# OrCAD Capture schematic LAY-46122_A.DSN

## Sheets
1 PAGE1: size A3; rev: 1; note: HIGH POWER MODULE
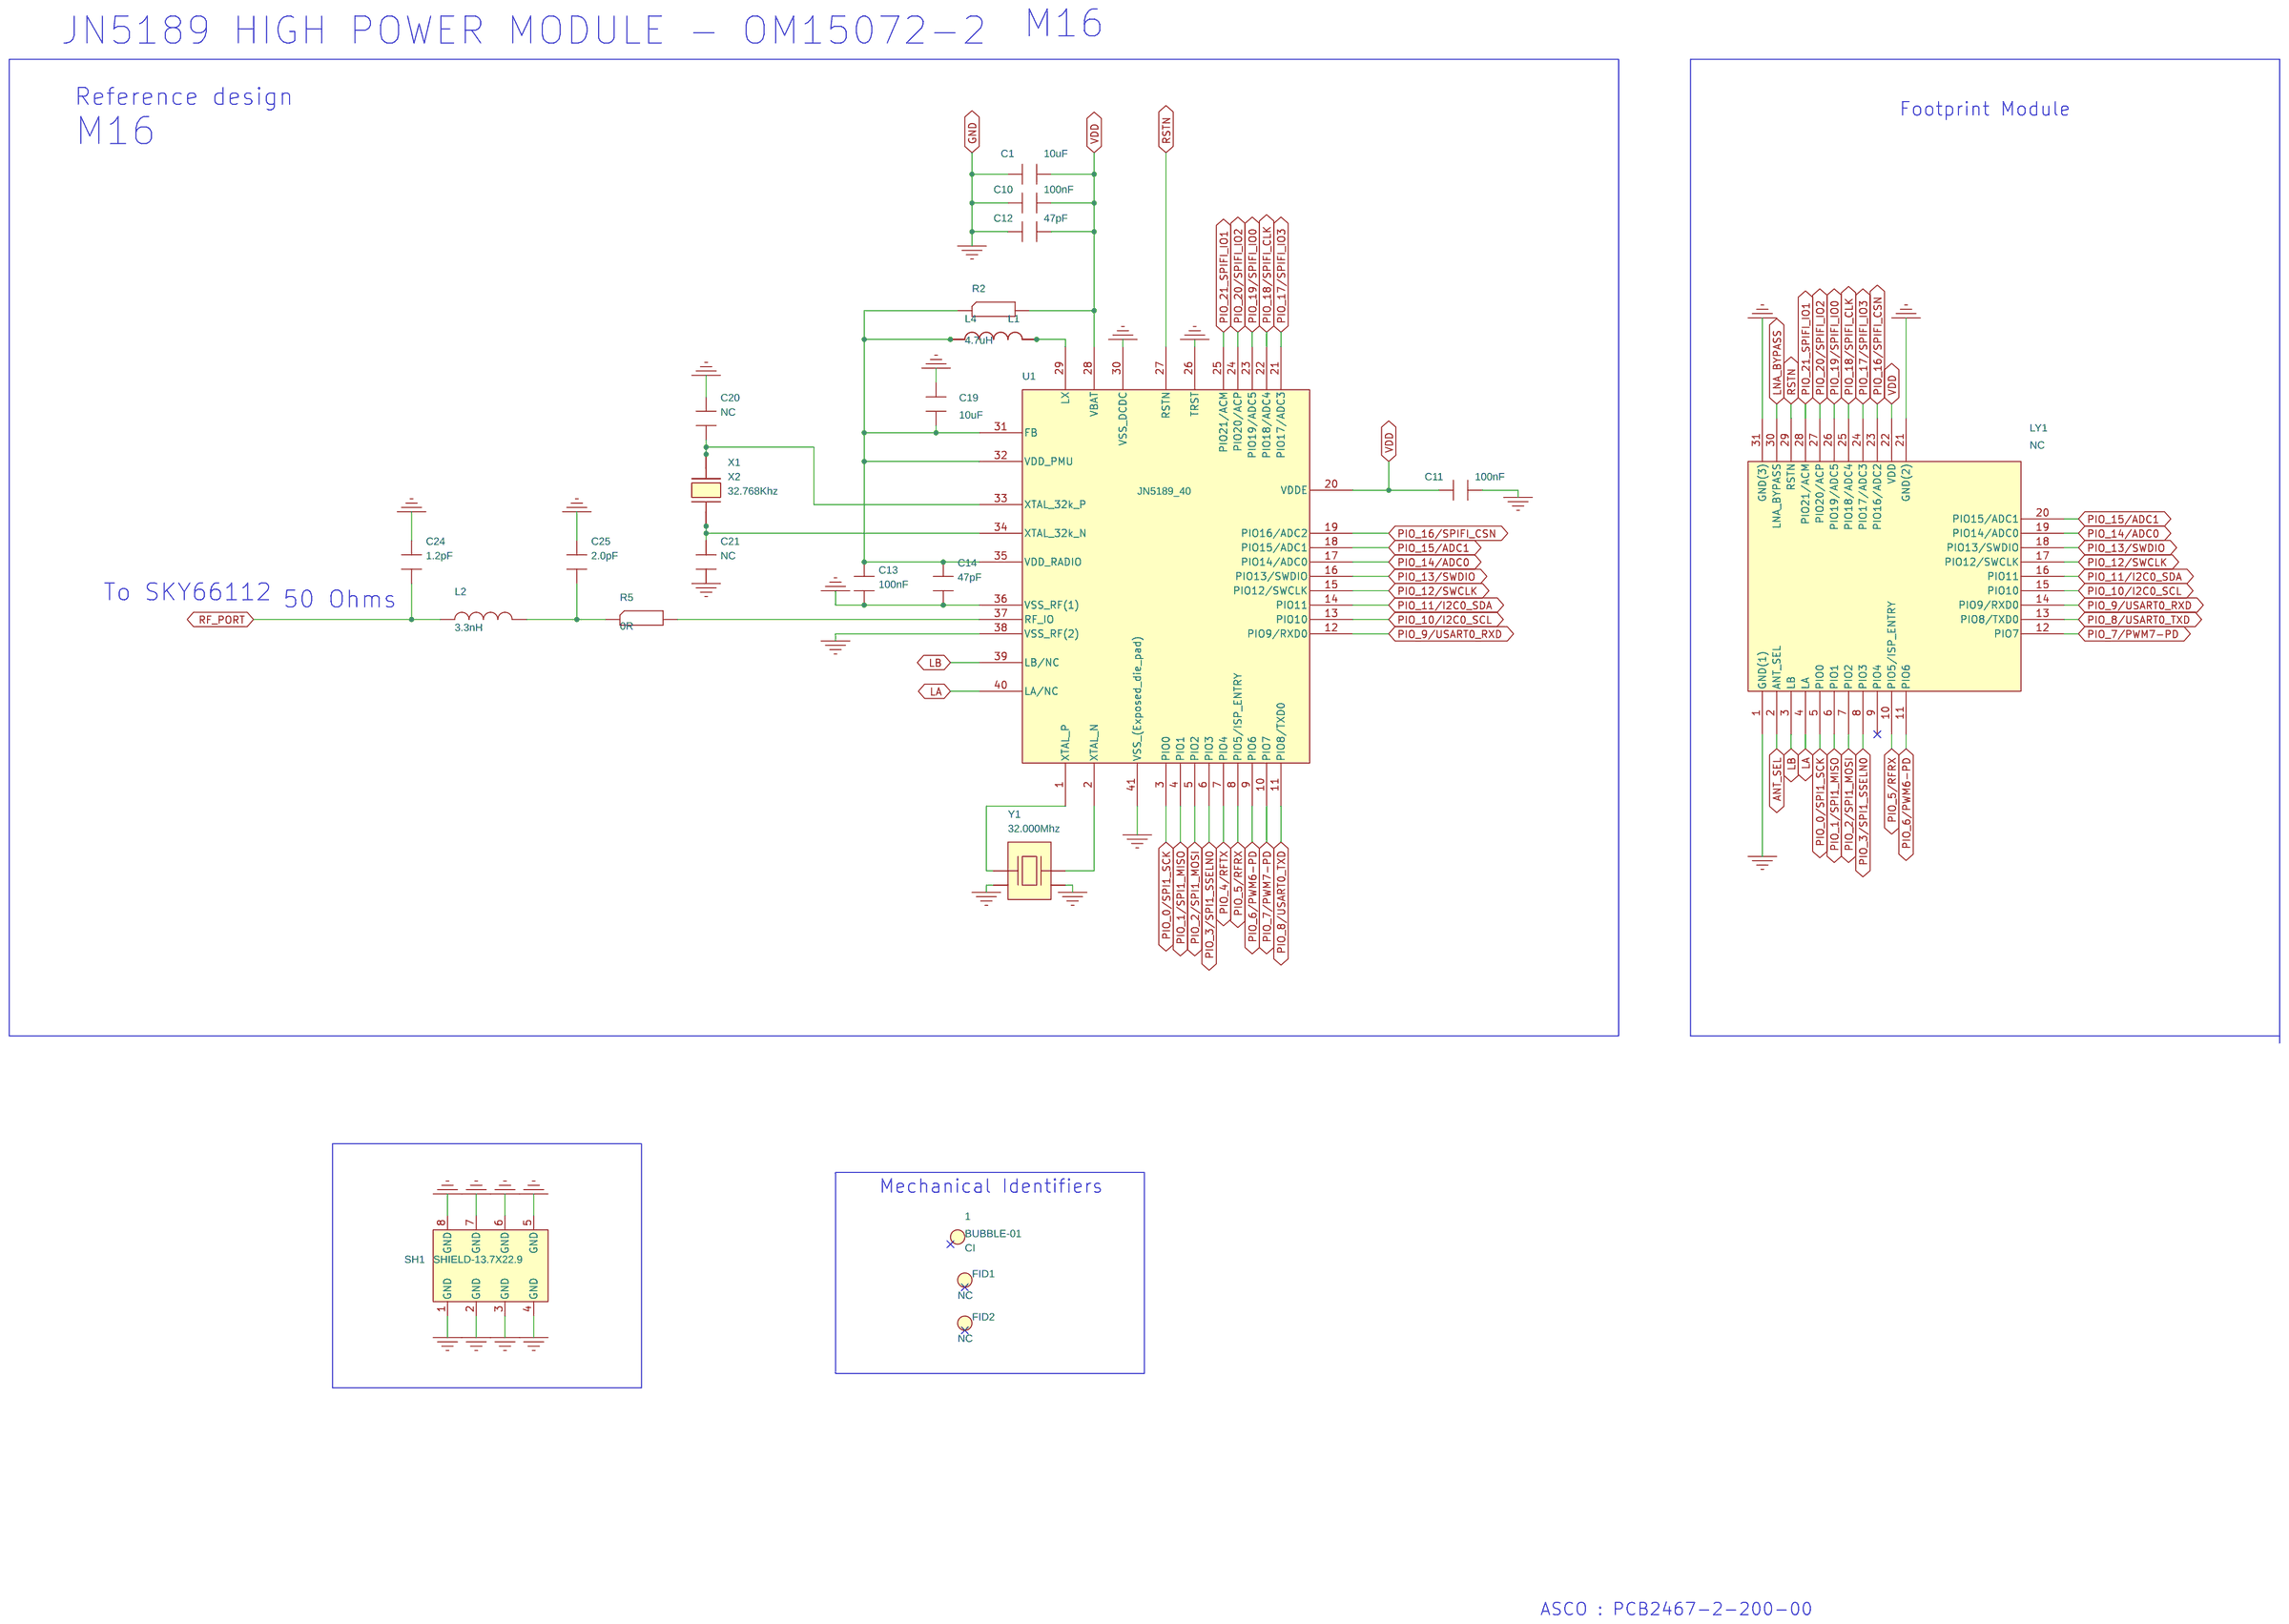
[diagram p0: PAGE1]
2 PAGE2: size A3; note: EXTERNAL_AMPLIFICATOR_MODULE
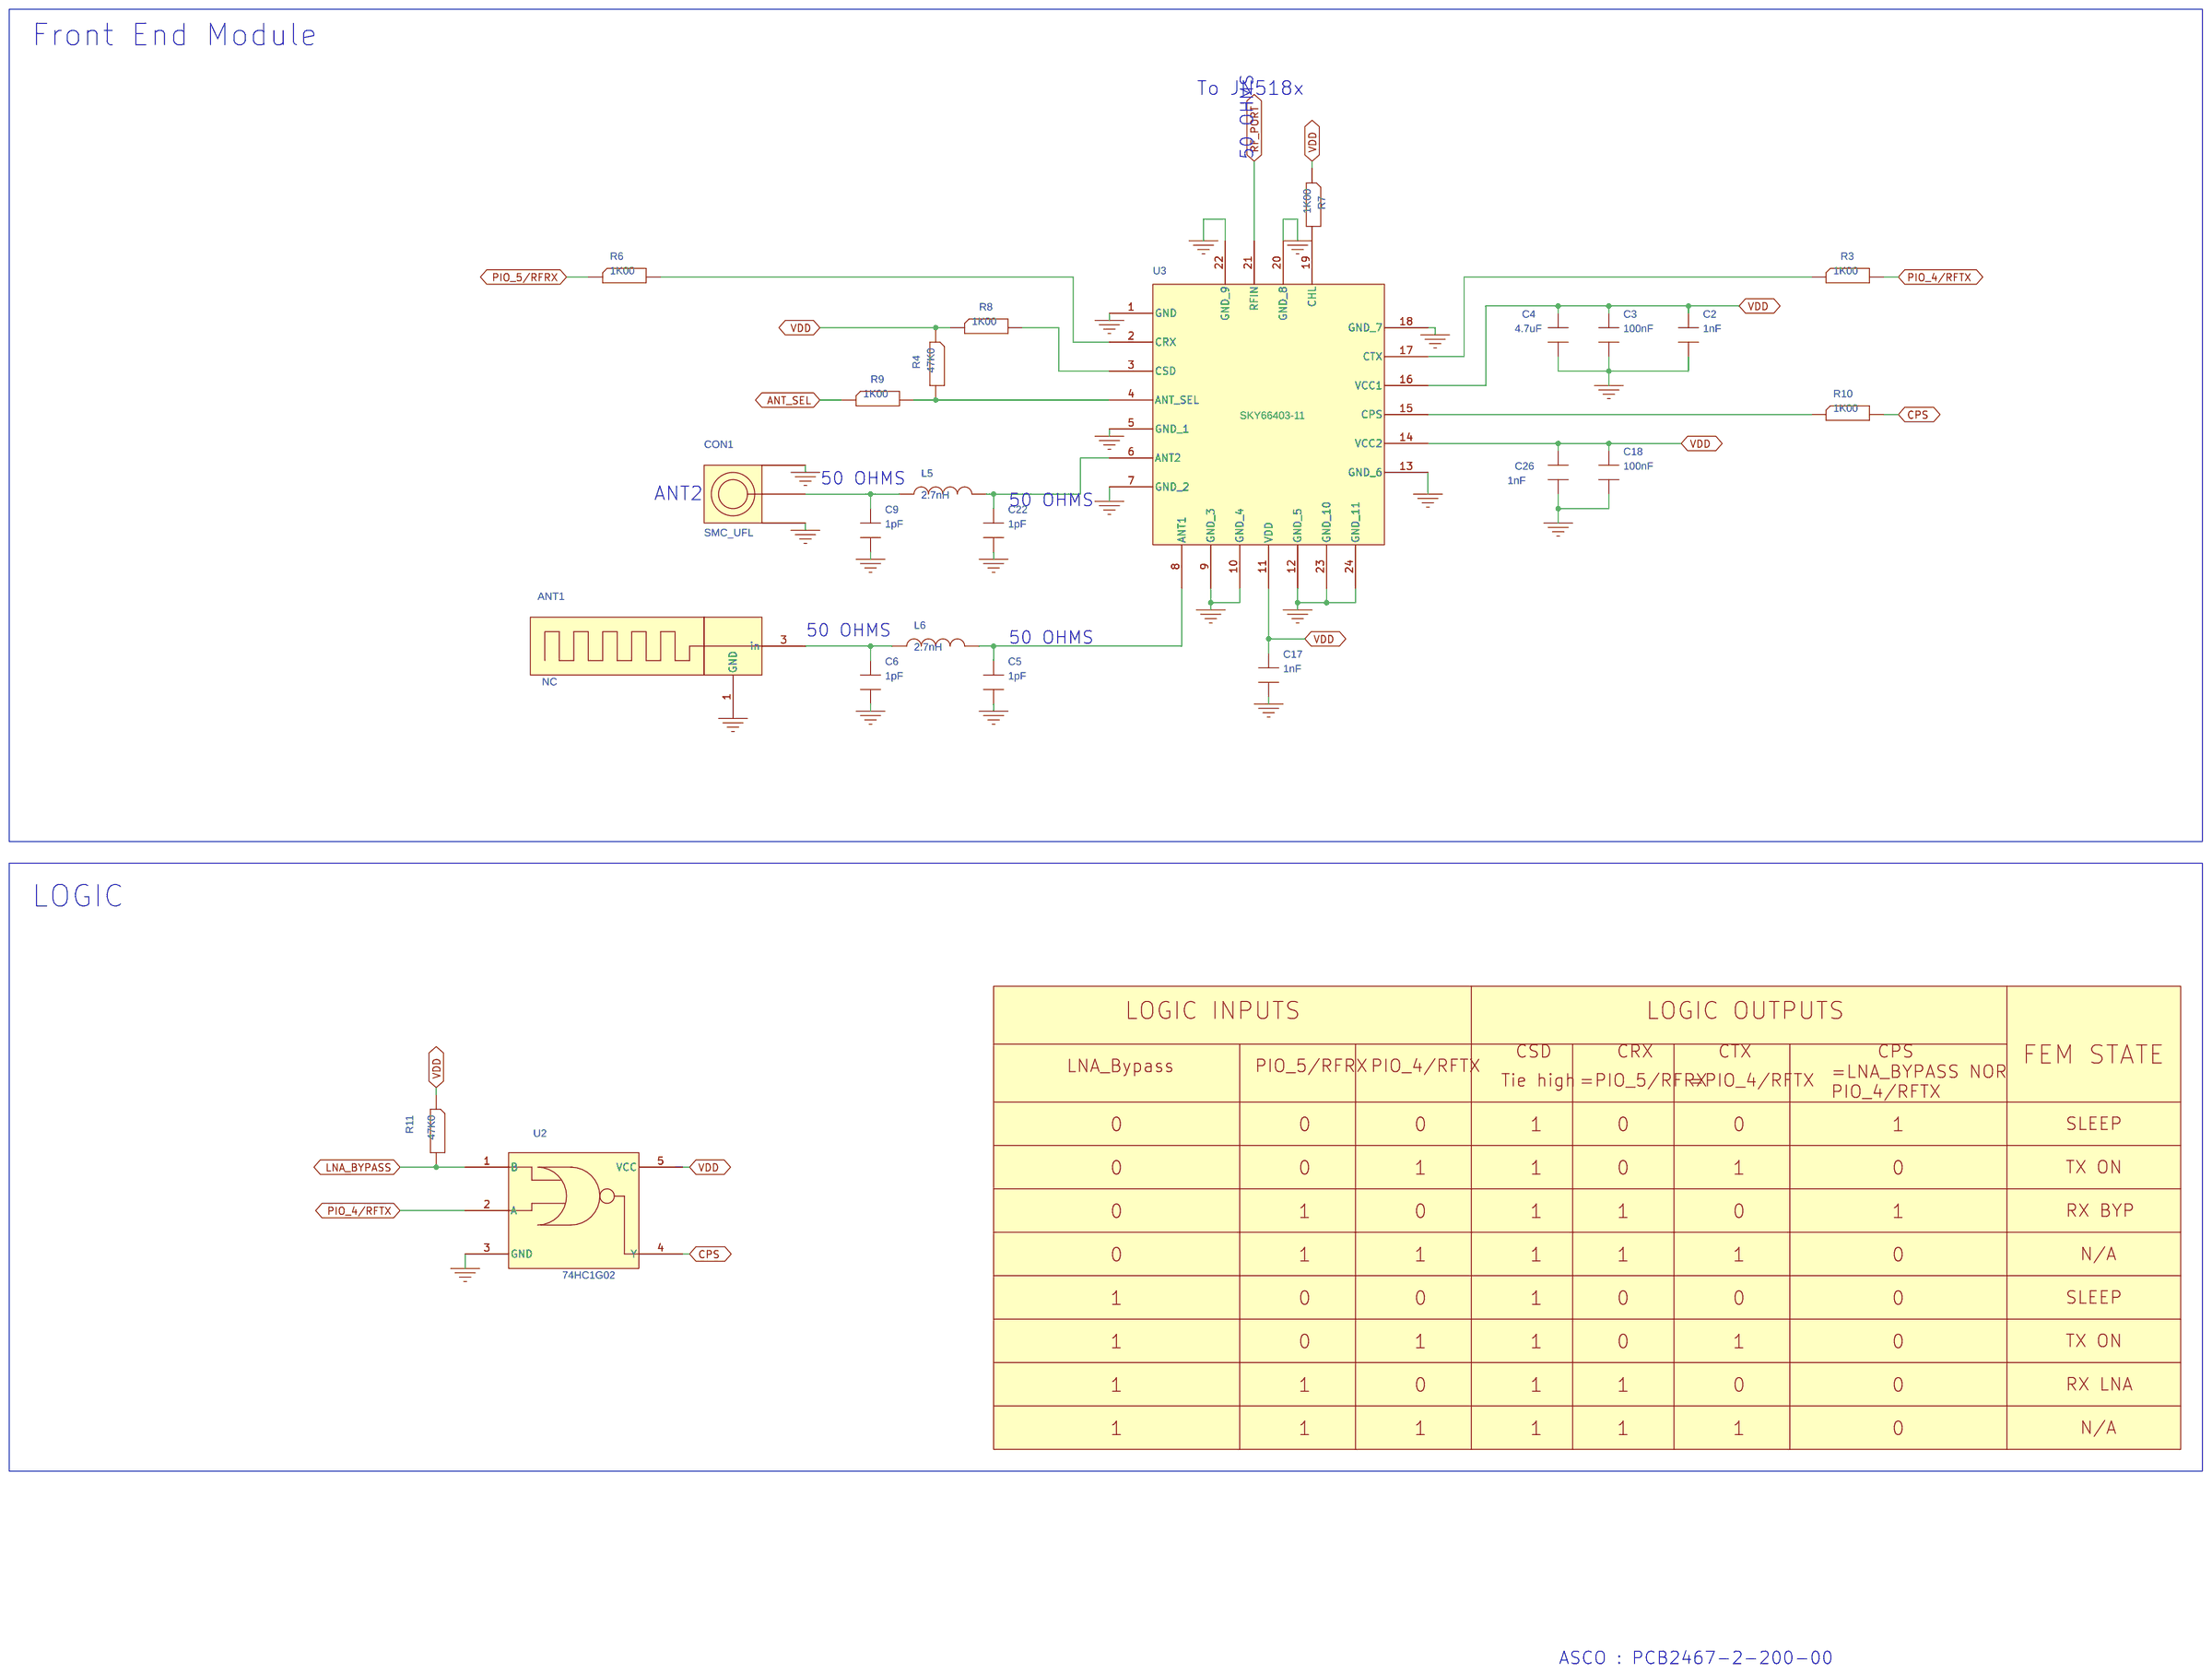
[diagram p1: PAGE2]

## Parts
sheet PAGE1
1  BUBBLE-01  [BUBBLE_DIAM8]
C1  10uF  [C0805]
C10  100nF  [C0402]
C11  100nF  [C0402]
C12  47pF  [C0402]
C13  100nF  [C0402]
C14  47pF  [C0402]
C19  10uF  [C0805]
C20  NC  [C0402]
C21  NC  [C0402]
C24  1.2pF  [C0402]
C25  2.0pF  [C0402]
FID1  NC  [FID1]
FID2  NC  [FID1]
L1  4,7uH_NC  [IND_CB_2518_2520]
L2  3.3nH  [SELF_0402]
L4  4.7uH  [0805C_IPCC]
LY1  NC  [LYRE_31PTS_CARRIER]
R2  NC  [R0402]
R5  0R  [R0402]
SH1  SHIELD-13.7X22.9  [shield_13mm7x22mm9]
U1  JN5189_40  [SOT618-1_HVQFN40_050_JN518x]
X1  32.768Khz_NC  [NX3215SA]
X2  32.768Khz  [NX2012SA]
Y1  32.000Mhz  [NX2016SA]
sheet PAGE2
2  Tableau
ANT1  NC  [pcb_ant_apps]
C2  1nF  [C0402]
C3  100nF  [C0402]
C4  4.7uF  [C0402]
C5  1pF  [C0402]
C6  1pF  [C0402]
C9  1pF  [C0402]
C17  1nF  [C0402]
C18  100nF  [C0402]
C22  1pF  [C0402]
C26  1nF  [C0402]
CON1  SMC_UFL  [SMC-UFL-R-SMT]
L5  2.7nH  [SELF_0402]
L6  2.7nH  [SELF_0402]
R3  1K00  [R0402]
R4  47K0  [R0402]
R6  1K00  [R0402]
R7  1K00  [R0402]
R8  1K00  [R0402]
R9  1K00  [R0402]
R10  1K00  [R0402]
R11  47K0  [R0402]
U2  74HC1G02  [SOT353]
U3  SKY66403-11  [SKY66403-11]

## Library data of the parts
1 = BUBBLE: Designation: Printed Circuit Board : OM15072-2 (NXP : module JN518X (HVQFN40) with External Ampli.); Manufacturer_reference: PCB2467-2; Part Number: 0-CI-001593; Part Type: BUBBLE-001_CI; Supplier: ASCO; TYPE: CI
C1 C19 = CAPA: Alt_Symbols: 0805C; Designation: Capacitor 0805 10uF 10% 10V X7R (-55°C+125°C); Gamme: X7R; MANUFACTURER_REFERENCE: MURATA (GRM21BR71A106KA73L); Package: 805; Part Number: 0-00-306046A; Supplier: FARNELL; Tension: 10V; Tol: 10%
C10 C11 C13 = CAPA: Alt_Symbols: 0402C; Designation: Capacitor 0402 100nF 10% 10V X7R (-55°C+125°C); Gamme: X7R; Package: 402; Part Number: 0-00-300053; Temp: (-55°C+125°C); Tension: 10V; Tol: 10%
C12 C14 = CAPA: Alt_Symbols: 0402C; Designation: Capacitor 0402 47pF 5% 25V COG/NPO (-55°C+125°C); Gamme: COG/NPO; MANUFACTURER_REFERENCE: MURATA (GRM1555C1E470JA01); Package: 402; Part Number: 0-00-300164C; Supplier: DIGIKEY CORPORATION; Temp: (-55°C+125°C); Tension: 25V; Tol: 5%
C20 C21 = CAPA: Alt_Symbols: 0402C; Designation: !!! NOT CONNECTED !!!; Package: 402; Part Number: 0-00-3NC_C0402
C24 = CAPA: Alt_Symbols: 0402C; Designation: Capacitor 0402 1.2pF +/-0.1pF 50V; Manufacturer_reference: MURATA (GRM1555C1H1R2BA01D); Package: 402; Part Number: 0-00-300040A; Supplier: RADIOSPARES; Tension: 50V; Tol: +/-0.1pF
C25 = CAPA: Alt_Symbols: 0402C; Designation: Capacitor 0402 2.0pF +/-0.1pF 50V; Package: 402; Part Number: 0-00-305251; Tension: 50V; Tol: +/-0.1pF
FID1 FID2 = MIRE: Designation: !!! Not Connected !!!; Part Number: 0-00-2MIRE_FID_NC; Part Type: MISC
L1 = SELF: Designation: !!! NOT CONNECTED !!! Inductor 1008/2520 4,7uH 800mA(Max) 380mOhms(Max) 20%; Manufacturer_reference: TAIYO YUDEN (MBMK2520H4R7M); Package: 1008; Part Number: 0-00-002246A_NC; Part Type: INDUCTOR; Temp: (-40°C to 125°C)
L2 = SELF: Designation: Inductor 0402 3.3nH +/-0.1nH 2A, Ron DC=30mOhms, Q=30, Resonance Freq=14.0 Ghz (-55°C to 125°C); Manufacturer_reference: MURATA (LQW15AN3N3B); Package: 402; Part Number: PN-LQW15AN3N3B; Part Type: L0402; Temp: (-55°C to 125°C)
L4 = SELF: Designation: Inductor 0805 4,7uH 300mA(Max) 340mOhms(Max) 20% (-55°C to 125°C); Manufacturer_reference: TDK (MLZ2012M4R7H); Package: 805; Part Number: 0-00-002803A; Part Type: L0805; Temp: (-40°C to 125°C)
LY1 = LYRE_MODJN518x_31PTS: Designation: !!! Not Connected !!!; Manufacturer_reference: NXP; Package: LYRE; Part Number: 0-00-2LYREMODJN518x_31_NC; Part Type: LYRE
R2 = RES: Designation: !!! NOT CONNECTED !!!; PACKAGE: 402; Part Number: 0-00-3NC_R0402
R5 = RES: Alt_Symbols: 0402R; Designation: Resistor 0402 0R - - -; PACKAGE: 402; Part Number: 0-00-301956; Type: CMS
SH1 = SHIELD_8PTS: Designation: !!! NOT CONNECTED !!!SHIELD : 13.7MM x 22.9MM; Manufacturer_reference: NXP; Package: SHIELD; Part Number: NC_0-00-204889; Part Type: SHIELD
U1 = JN518x_QFN40: Designation: Integrated Circuit JN5189 (QFN40); Manufacturer_reference: NXP (JN5189) (QFN40); Package: HVQFN40; Part Number: 0-00-404672; Part Type: IC
X1 = XTAL: Designation: !!! NOT CONNECTED !!! Crystal 32.768 KHz +/-20ppm (Automotive version) (Load Cap. 12.5pF) (-40°C to 125°C); Manufacturer_reference: NDK (NX3215SA-32.768K-STD-MUS-2); Part Number: 0-00-403987_NC; Part Type: CLOCK; Temp: (-40°C to 125°C)
X2 = XTAL: Designation: Crystal 32.768 KHz +/-20ppm (Automotive version) (Load Cap. 6.0pF) (-40°C to 125°C); Manufacturer_reference: NDK (NX2012SA 32.768KHZ EXS00A-MU01089 6pF); Part Number: 0-00-404675; Part Type: CLOCK
Y1 = XTAL_NX2016_4P: Designation: Crystal 32 MHz +/-40ppm (automotive version) (Load Cap. 6.0pF) (-40°C to 125°C); Manufacturer_reference: NDK (NX2016SA 32MHZ EXS00A-CS11213 6PF); Part Number: 0-00-404674; Part Type: CLOCK
2 = Tableau_4: Designation: Tableau corespondance Logique
ANT1 = ANTENNA_JN518x: Alt_Symbols: pcb_ant_apps_flip; Designation: !!! COPPER PRINTED BOARD !!!; Package: ANTENNA; Part Number: 0-00-0ANT_MOD_JN518x; Part Type: MISC
C2 C17 C26 = CAPA: Alt_Symbols: 0402C; Designation: Capacitor 0402 1nF 10% 50V X7R (-55°C+125°C); Gamme: X7R; MANUFACTURER_REFERENCE: YAGEO (PHYCOMP) (CC0402KRX7R9BB102); Package: 402; Part Number: 0-00-300099G; Supplier: FARNELL; Temp: (-55°C+125°C); Tension: 50V; Tol: 10%
C3 C18 = CAPA: Alt_Symbols: 0402C; Designation: Capacitor 0402 100nF 10% 25V X5R (-55°C+85°C); Gamme: X5R; Package: 402; Part Number: 0-00-300057; Temp: (-55°C+85°C); Tension: 25V; Tol: 10%
C4 = CAPA: Alt_Symbols: 0402C; Designation: Capacitor 0402 4.7uF 10% 10V X5R (-55°C+85°C); Gamme: X5R; Package: 402; Part Number: 0-00-300143; Tension: 10V; Tol: 10%
C5 C6 C9 C22 = CAPA: Alt_Symbols: 0402C; Designation: Capacitor 0402 1pF +/-0.25pF 50V; MANUFACTURER_REFERENCE: MURATA (GJM1555C1H1R0CB01D), YAGEO (PHYCOMP) (CC0402CRNPO9BN1R0); Package: 402; Part Number: 0-00-300102B; Supplier: DIGIKEY CORPORATION; Tension: 50V; Tol: +/-0.25pF
CON1 = SMC_UFL: Designation: Coaxial Connector SMC (uFL); Manufacturer_reference: HIROSE (U.FL-R-SMT-1(10)), Hirose Electric Co Ltd (U.FL-R-SMT-1(10)), HRS (HIROSE) (U.FL-R-SMT-1(10)); Part Number: 0-00-201187A; Part Type: CONNECTOR
L5 L6 = SELF: Designation: Inductor 0402 2.7nH +/-0,3nH 300mA, Ron DC=17mOhms, Resonance Freq=6.0 Ghz (-55°C to 125°C); Manufacturer_reference: MURATA (LQG15HN2N7S02); Package: 402; Part Number: 0-00-002025A; Part Type: L0402; Temp: (-55°C to 125°C)
R3 R6-R10 = RES: Alt_Symbols: 0402R; Designation: Resistor 0402 1K00 5% 200ppm -; MANUFACTURER_REFERENCE: YAGEO (PHYCOMP) (RC0402JR-071KL); PACKAGE: 402; PPM: 200ppm; Part Number: 0-00-302005C; SUPPLIER: FARNELL; TOL: 5%
R4 R11 = RES: Alt_Symbols: 0402R; Designation: Resistor 0402 47K0 1% 100ppm -; MANUFACTURER_REFERENCE: YAGEO (PHYCOMP) (RC0402FR-0747KL); PACKAGE: 402; PPM: 100ppm; Part Number: 0-00-302104A; SUPPLIER: FARNELL; TOL: 1%
U2 = 74HC1G02: Designation: Integrated Circuit Logique 74HC1G02 (SOT353); Manufacturer_reference: NXP (74HC1G02); Package: SOT353-1; Part Number: 0-00-404003; Part Type: IC; Temp: (-40°C to +125°C)
U3 = SKY66112-11: Designation: SKYWORKS,2.4GHz ZIGBEE/ Smart energy front Module; Manufacturer_reference: SKYWORKS (SKY66403-11); Part Number: PN-SKY66403-11; Part Type: IC

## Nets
GND: ANT1.1(GND) C1.1 C2.2 C3.2 C4.2 C5.2 C6.2 C9.2 C10.1 C11.2 C12.1 C13.2 C14.2 C17.2 C18.2 C19.2 C20.1 C21.2 C22.2 C24.1 C25.1 C26.2 CON1.2 CON1.3 LY1.1(GND(1)) LY1.21(GND(2)) LY1.31(GND(3)) SH1.1(GND) SH1.2(GND) SH1.3(GND) SH1.4(GND) SH1.5(GND) SH1.6(GND) SH1.7(GND) SH1.8(GND) U1.26(TRST) U1.30(VSS_DCDC) U1.36(VSS_RF(1)) U1.38(VSS_RF(2)) U1.41(VSS_(Exposed_die_pad)) U2.3(GND) U3.1(GND) U3.5(GND_1) U3.7(GND_2) U3.9(GND_3) U3.10(GND_4) U3.12(GND_5) U3.13(GND_6) U3.18(GND_7) U3.20(GND_8) U3.22(GND_9) U3.23(GND_10) U3.24(GND_11) Y1.2 Y1.4
VDD: C1.2 C2.1 C3.1 C4.1 C10.2 C11.1 C12.2 C17.1 C18.1 C26.1 LY1.22(VDD) R2.2 R4.1 R7.1 R8.1 R11.1 U1.20(VDDE) U1.28(VBAT) U2.5(VCC) U3.11(VDD) U3.14(VCC2) U3.16(VCC1)
ANT_SEL: LY1.2(ANT_SEL) R9.1
CPS: R10.2 U2.4(Y)
LA: LY1.4(LA) U1.40(LA/NC)
LB: LY1.3(LB) U1.39(LB/NC)
LNA_BYPASS: LY1.30(LNA_BYPASS) R11.2 U2.1(B)
PIO_0/SPI1_SCK: LY1.5(PIO0) U1.3(PIO0)
PIO_1/SPI1_MISO: LY1.6(PIO1) U1.4(PIO1)
PIO_2/SPI1_MOSI: LY1.7(PIO2) U1.5(PIO2)
PIO_3/SPI1_SSELN0: LY1.8(PIO3) U1.6(PIO3)
PIO_4/RFTX: R3.2 U1.7(PIO4) U2.2(A)
PIO_5/RFRX: LY1.10(PIO5/ISP_ENTRY) R6.1 U1.8(PIO5/ISP_ENTRY)
PIO_6/PWM6-PD: LY1.11(PIO6) U1.9(PIO6)
PIO_7/PWM7-PD: LY1.12(PIO7) U1.10(PIO7)
PIO_8/USART0_TXD: LY1.13(PIO8/TXD0) U1.11(PIO8/TXD0)
PIO_9/USART0_RXD: LY1.14(PIO9/RXD0) U1.12(PIO9/RXD0)
PIO_10/I2C0_SCL: LY1.15(PIO10) U1.13(PIO10)
PIO_11/I2C0_SDA: LY1.16(PIO11) U1.14(PIO11)
PIO_12/SWCLK: LY1.17(PIO12/SWCLK) U1.15(PIO12/SWCLK)
PIO_13/SWDIO: LY1.18(PIO13/SWDIO) U1.16(PIO13/SWDIO)
PIO_14/ADC0: LY1.19(PIO14/ADC0) U1.17(PIO14/ADC0)
PIO_15/ADC1: LY1.20(PIO15/ADC1) U1.18(PIO15/ADC1)
PIO_16/SPIFI_CSN: LY1.23(PIO16/ADC2) U1.19(PIO16/ADC2)
PIO_17/SPIFI_IO3: LY1.24(PIO17/ADC3) U1.21(PIO17/ADC3)
PIO_18/SPIFI_CLK: LY1.25(PIO18/ADC4) U1.22(PIO18/ADC4)
PIO_19/SPIFI_IO0: LY1.26(PIO19/ADC5) U1.23(PIO19/ADC5)
PIO_20/SPIFI_IO2: LY1.27(PIO20/ACP) U1.24(PIO20/ACP)
PIO_21_SPIFI_IO1: LY1.28(PIO21/ACM) U1.25(PIO21/ACM)
RF_PORT: C24.2 L2.1 U3.21(RFIN)
RSTN: LY1.29(RSTN) U1.27(RSTN)
N16822568: C5.1 L6.2 U3.8(ANT1)
N16830522: L1.2 L4.2 U1.29(LX)
N16830681: U1.1(XTAL_P) Y1.1
N16830719: C25.2 L2.2 R5.1
N16830729: R5.2 U1.37(RF_IO)
N16830755: C13.1 C14.1 C19.1 L1.1 L4.1 R2.1 U1.31(FB) U1.32(VDD_PMU) U1.35(VDD_RADIO)
N16830775: C20.2 U1.33(XTAL_32k_P) X1.1 X2.1
N16831242: C22.1 L5.2 U3.6(ANT2)
N16832450: C9.1 CON1.1 L5.1
N16832469: C21.1 U1.34(XTAL_32k_N) X1.2 X2.2
N16839365: R3.1 U3.17(CTX)
N16842652: U1.2(XTAL_N) Y1.3
N16847933: R8.2 U3.3(CSD)
N16848100: R10.1 U3.15(CPS)
N16852723: R6.2 U3.2(CRX)
N16869758: ANT1.3(in) C6.1 L6.1
N16876581: R4.2 R9.2 U3.4(ANT_SEL)
N16927390: R7.2 U3.19(CHL)

Not connected (* = marked no-connect by the designer): 1 1*; FID1 1*; FID2 1*; LY1 9(PIO4)*

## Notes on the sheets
sheet 1
- M16
- JN5189 HIGH POWER MODULE - OM15072-2
- Reference design
- M16
- Footprint Module
- To SKY66112
- 50 Ohms
- Mechanical Identifiers
- ASCO : PCB2467-2-200-00
sheet 2
- Front End Module
- To JN518x
- 50 OHMS
- ANT2
- 50 OHMS
- 50 OHMS
- 50 OHMS
- 50 OHMS
- LOGIC
- ASCO : PCB2467-2-200-00
